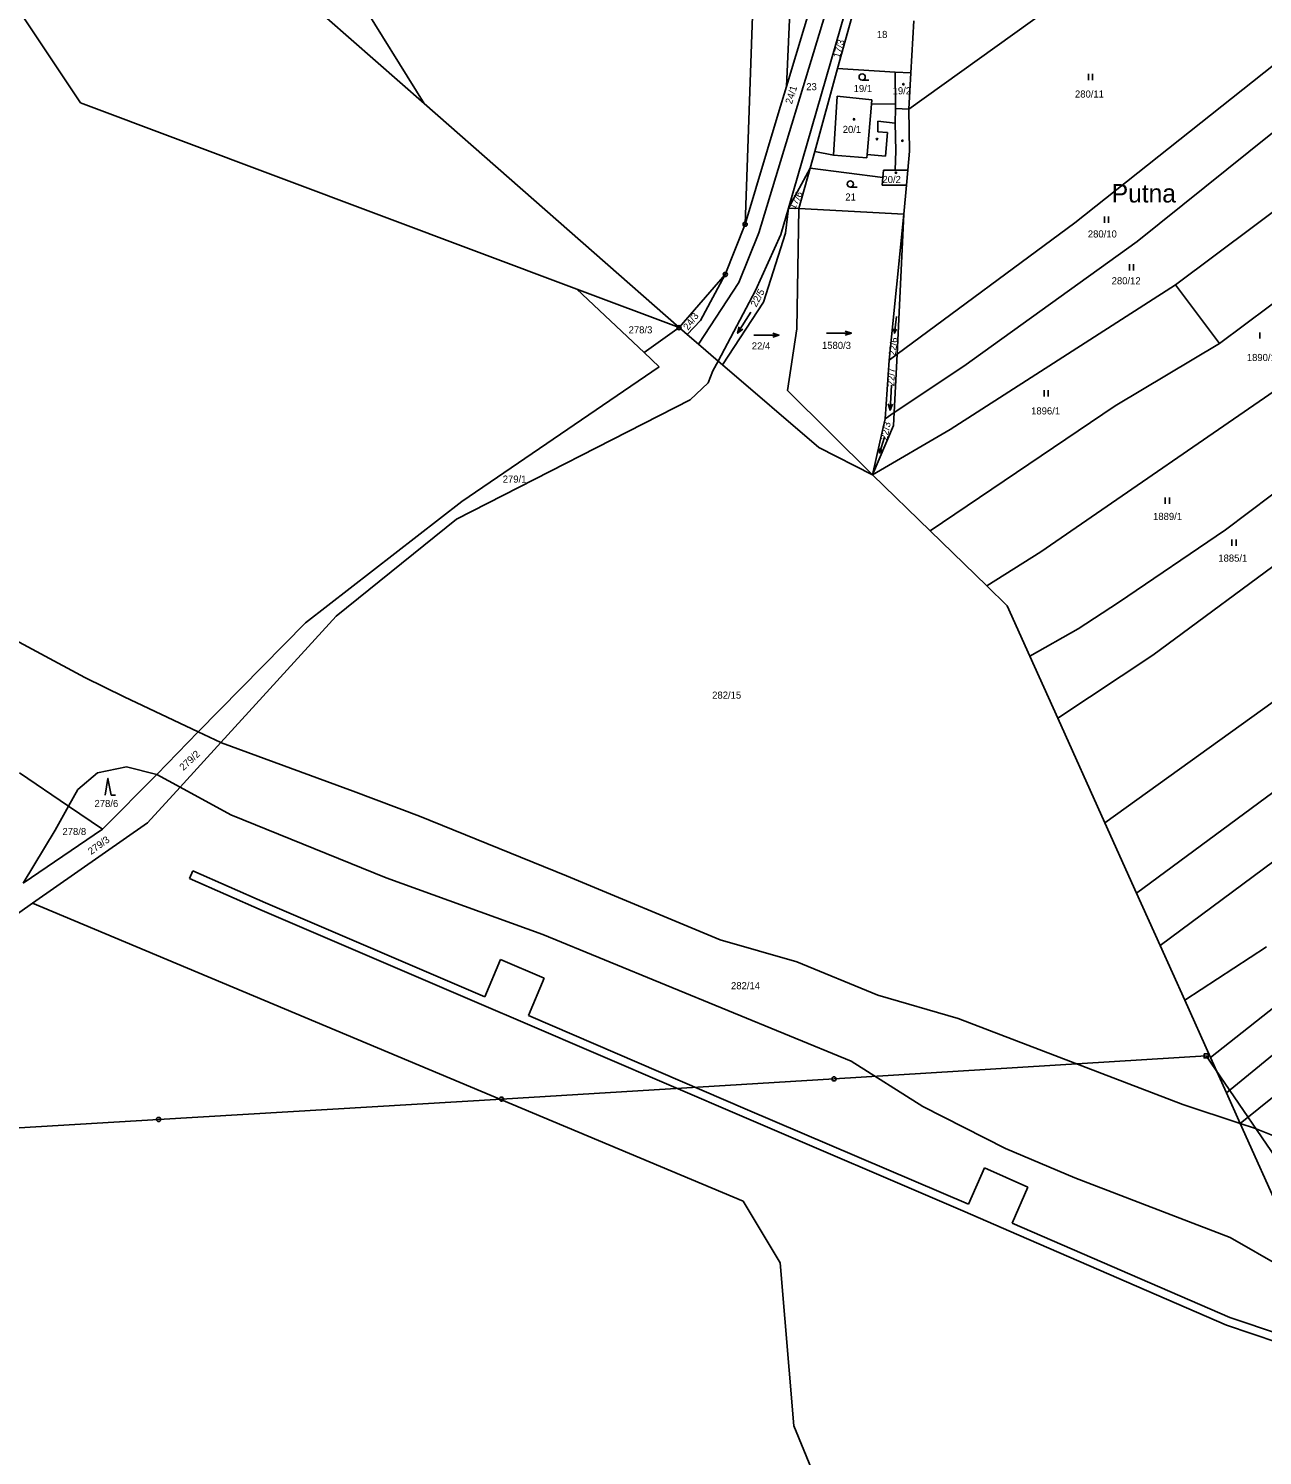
# Model space of a CAD drawing. Extents: x -762263 to -760336, y -1154405 to -1152076.
# Drawn here: x -761992.3 to -761696.3, y -1152903.3 to -1152561.1 of the extents above; entities that cross this region are included whole.
import ezdxf

# ---------------------------------------------------------------- set-up
doc = ezdxf.new("R2010")
doc.units = 0
for name, color, linetype in [('Vrstva 1', 7, 'Continuous'), ('Vrstva 12', 7, 'Continuous'), ('Vrstva 15', 7, 'Continuous'), ('Vrstva 18', 7, 'Continuous'), ('Vrstva 19', 7, 'Continuous'), ('Vrstva 24', 7, 'Continuous'), ('Vrstva 25', 7, 'Continuous'), ('Vrstva 26', 7, 'Continuous'), ('Vrstva 4', 7, 'Continuous'), ('Vrstva 6', 7, 'Continuous')]:
    doc.layers.add(name, color=color, linetype=linetype)

msp = doc.modelspace()

# ---------------------------------------------------------------- linework, layer by layer
at = {"layer": 'Vrstva 1'}
for p, q in [((-761816.98, -1152512.11), (-761820.4, -1152608.02)), ((-761971.53, -1152513.93), (-761897.36, -1152579.11)), ((-761817.12, -1152610.13), (-761793.65, -1152532.71)), ((-762008.34, -1152536.1), (-761979.81, -1152578.93)), ((-761810.02, -1152604.15), (-761790.04, -1152534.85)), ((-761721.98, -1152537.97), (-761781.14, -1152580.45)), ((-761798.23, -1152570.67), (-761792.59, -1152550.46)), ((-761780.62, -1152571.75), (-761779.95, -1152559.21)), ((-761803.71, -1152590.57), (-761798.23, -1152570.67)), ((-761798.23, -1152570.67), (-761784.38, -1152571.52)), ((-761784.38, -1152571.52), (-761780.62, -1152571.75)), ((-761784.32, -1152579.13), (-761784.38, -1152571.52)), ((-761780.62, -1152571.75), (-761781.14, -1152580.45)), ((-761860.79, -1152623.61), (-761979.81, -1152578.93)), ((-761897.36, -1152579.11), (-761836.24, -1152632.82)), ((-761798.33, -1152577.35), (-761799.22, -1152591.49)), ((-761790, -1152578.21), (-761798.33, -1152577.35)), ((-761790.1, -1152579.22), (-761790, -1152578.21)), ((-761784.32, -1152579.13), (-761790.1, -1152579.22)), ((-761784.31, -1152580.27), (-761784.32, -1152579.13)), ((-761781.14, -1152580.45), (-761784.31, -1152580.27)), ((-761780.94, -1152590.48), (-761781.14, -1152580.45)), ((-761804.8, -1152594.57), (-761803.71, -1152590.57)), ((-761799.22, -1152591.49), (-761803.71, -1152590.57)), ((-761781.36, -1152595.08), (-761780.94, -1152590.48)), ((-761670.53, -1152587.64), (-761717.16, -1152622.54)), ((-761807.48, -1152604.29), (-761804.8, -1152594.57)), ((-761804.8, -1152594.57), (-761787.37, -1152596.85)), ((-761787.37, -1152596.85), (-761787.55, -1152598.65)), ((-761787.19, -1152595.04), (-761787.37, -1152596.85)), ((-761784.44, -1152595.06), (-761787.19, -1152595.04)), ((-761781.36, -1152595.08), (-761784.44, -1152595.06)), ((-761781.69, -1152598.66), (-761781.36, -1152595.08)), ((-761781.69, -1152598.66), (-761787.55, -1152598.65)), ((-761782.33, -1152605.63), (-761781.69, -1152598.66)), ((-761810.02, -1152604.15), (-761811.86, -1152610.53)), ((-761807.48, -1152604.29), (-761810.02, -1152604.15)), ((-761782.33, -1152605.63), (-761807.48, -1152604.29)), ((-761706.64, -1152636.65), (-761659.83, -1152601.72)), ((-761825.15, -1152620.07), (-761820.4, -1152608.02)), ((-761782.33, -1152605.63), (-761783.97, -1152639.19)), ((-761821.89, -1152622.04), (-761817.12, -1152610.13)), ((-761817.91, -1152623.93), (-761811.86, -1152610.53)), ((-761836.24, -1152632.82), (-761825.15, -1152620.07)), ((-761836.24, -1152632.82), (-761860.79, -1152623.61)), ((-761844.63, -1152638.78), (-761860.79, -1152623.61)), ((-761831.6, -1152636.81), (-761821.89, -1152622.04)), ((-761826.89, -1152640.86), (-761817.91, -1152623.93)), ((-761706.64, -1152636.65), (-761717.16, -1152622.54)), ((-761836.24, -1152632.82), (-761844.63, -1152638.78)), ((-761834.27, -1152634.51), (-761836.24, -1152632.82)), ((-761831.6, -1152636.81), (-761834.27, -1152634.51)), ((-761840.99, -1152642.2), (-761844.63, -1152638.78)), ((-761831.6, -1152636.81), (-761826.89, -1152640.86)), ((-761888.32, -1152674.54), (-761840.99, -1152642.2)), ((-761828.12, -1152643.18), (-761826.89, -1152640.86)), ((-761826.89, -1152640.86), (-761825.81, -1152641.78)), ((-761802.74, -1152661.6), (-761825.81, -1152641.78)), ((-761783.97, -1152639.19), (-761784.65, -1152653.15)), ((-761829.24, -1152646.1), (-761828.12, -1152643.18)), ((-761833.6, -1152650.17), (-761829.24, -1152646.1)), ((-761889.59, -1152678.77), (-761833.6, -1152650.17)), ((-761784.65, -1152653.15), (-761784.81, -1152656.32)), ((-761789.86, -1152668.14), (-761784.81, -1152656.32)), ((-761802.74, -1152661.6), (-761789.86, -1152668.14)), ((-761789.86, -1152668.14), (-761776.05, -1152681.57)), ((-761925.83, -1152703.65), (-761888.32, -1152674.54)), ((-761889.59, -1152678.77), (-761918.45, -1152702.03)), ((-761776.05, -1152681.57), (-761762.46, -1152694.78)), ((-761635.48, -1152680.7), (-761734.11, -1152751.6)), ((-761762.46, -1152694.78), (-761757.53, -1152699.58)), ((-761752.1, -1152711.64), (-761757.53, -1152699.58)), ((-762008.53, -1152700.8), (-761978.76, -1152716.74)), ((-761925.83, -1152703.65), (-761951.56, -1152729.76)), ((-761918.45, -1152702.03), (-761946.15, -1152732.31)), ((-761745.41, -1152726.49), (-761752.1, -1152711.64)), ((-761978.76, -1152716.74), (-761969.35, -1152721.4)), ((-761951.56, -1152729.76), (-761969.35, -1152721.4)), ((-761734.11, -1152751.6), (-761745.41, -1152726.49)), ((-761951.56, -1152729.76), (-761961.5, -1152739.99)), ((-761946.15, -1152732.31), (-761951.56, -1152729.76)), ((-761946.15, -1152732.31), (-761955.94, -1152743.01)), ((-761946.15, -1152732.31), (-761945.97, -1152732.39)), ((-761945.97, -1152732.39), (-761914.39, -1152744)), ((-761994.44, -1152739.57), (-761982.68, -1152747.59)), ((-761980.46, -1152743.57), (-761975.76, -1152739.58)), ((-761975.76, -1152739.58), (-761968.74, -1152738.14)), ((-761961.5, -1152739.99), (-761974.57, -1152753.12)), ((-761961.5, -1152739.99), (-761968.74, -1152738.14)), ((-761955.94, -1152743.01), (-761961.5, -1152739.99)), ((-761982.68, -1152747.59), (-761980.46, -1152743.57)), ((-761955.94, -1152743.01), (-761963.76, -1152751.56)), ((-761955.94, -1152743.01), (-761943.75, -1152749.64)), ((-761914.39, -1152744), (-761898.53, -1152749.98)), ((-761985.87, -1152753.36), (-761982.68, -1152747.59)), ((-761974.57, -1152753.12), (-761982.68, -1152747.59)), ((-761991.29, -1152770.87), (-761963.76, -1152751.56)), ((-761943.75, -1152749.64), (-761906.53, -1152764.81)), ((-761898.53, -1152749.98), (-761863.26, -1152764.27)), ((-761734.11, -1152751.6), (-761726.5, -1152768.5)), ((-761974.57, -1152753.12), (-761993.53, -1152766.06)), ((-761993.53, -1152766.06), (-761985.87, -1152753.36)), ((-761952.86, -1152763.13), (-761953.66, -1152764.96)), ((-761953.66, -1152764.96), (-761936.2, -1152772.6)), ((-761935.4, -1152770.77), (-761952.86, -1152763.13)), ((-761906.53, -1152764.81), (-761868.88, -1152778.36)), ((-761863.26, -1152764.27), (-761826.38, -1152779.66)), ((-761726.5, -1152768.5), (-761720.86, -1152781.03)), ((-762001.57, -1152778.08), (-761991.29, -1152770.87)), ((-761820.89, -1152842.32), (-761991.29, -1152770.87)), ((-761882.87, -1152793.3), (-761935.4, -1152770.77)), ((-761936.2, -1152772.6), (-761883.65, -1152795.13)), ((-761868.88, -1152778.36), (-761794.95, -1152808.74)), ((-761826.38, -1152779.66), (-761808, -1152784.91)), ((-761720.86, -1152781.03), (-761714.94, -1152794.16)), ((-761879.04, -1152784.38), (-761882.87, -1152793.3)), ((-761868.56, -1152788.88), (-761879.04, -1152784.38)), ((-761808, -1152784.91), (-761788.59, -1152792.9)), ((-761872.39, -1152797.8), (-761868.56, -1152788.88)), ((-761883.65, -1152795.13), (-761873.18, -1152799.63)), ((-761788.59, -1152792.9), (-761769.32, -1152798.54)), ((-761714.94, -1152794.16), (-761708.78, -1152807.84)), ((-761873.18, -1152799.63), (-761820.62, -1152822.22)), ((-761819.83, -1152820.39), (-761872.39, -1152797.8)), ((-761769.32, -1152798.54), (-761715.38, -1152819.17)), ((-761794.95, -1152808.74), (-761777.78, -1152819.59)), ((-761708.78, -1152807.84), (-761704.93, -1152816.38)), ((-761704.93, -1152816.38), (-761701.64, -1152823.7)), ((-761777.78, -1152819.59), (-761757.91, -1152829.7)), ((-761715.38, -1152819.17), (-761701.64, -1152823.7)), ((-761820.62, -1152822.22), (-761767.61, -1152844.9)), ((-761766.8, -1152843.07), (-761819.83, -1152820.39)), ((-761691.51, -1152846.21), (-761701.64, -1152823.7)), ((-761701.64, -1152823.7), (-761698.2, -1152824.84)), ((-761698.2, -1152824.84), (-761679.85, -1152832.21)), ((-761757.91, -1152829.7), (-761741.31, -1152836.75)), ((-761762.99, -1152834.37), (-761766.8, -1152843.07)), ((-761752.55, -1152838.94), (-761762.99, -1152834.37)), ((-761741.31, -1152836.75), (-761704.08, -1152851.01)), ((-761756.36, -1152847.64), (-761752.55, -1152838.94)), ((-761811.96, -1152857.14), (-761820.89, -1152842.32)), ((-761767.61, -1152844.9), (-761757.16, -1152849.47)), ((-761757.16, -1152849.47), (-761704.92, -1152872.08)), ((-761704.12, -1152870.25), (-761756.36, -1152847.64)), ((-761704.08, -1152851.01), (-761691.53, -1152858.2)), ((-761808.73, -1152896.24), (-761811.96, -1152857.14)), ((-761691.97, -1152874.29), (-761704.12, -1152870.25)), ((-761704.92, -1152872.08), (-761692.6, -1152876.19)), ((-761769.11, -1152991.53), (-761808.73, -1152896.24))]:
    msp.add_line(p, q, dxfattribs=at)
at = {"layer": 'Vrstva 12'}
for p, q in [((-761709.8, -1152807.49), (-761799.07, -1152813)), ((-761644.75, -1152902.92), (-761709.8, -1152807.49)), ((-761799.07, -1152813), (-761878.83, -1152817.85)), ((-761878.83, -1152817.85), (-761961.09, -1152822.73)), ((-761961.09, -1152822.73), (-762045.29, -1152827.8))]:
    msp.add_line(p, q, dxfattribs=at)
at = {"layer": 'Vrstva 24'}
for centre, radius in [((-761820.4, -1152608.02), 0.5), ((-761820.4, -1152608.02), 0.1), ((-761825.15, -1152620.07), 0.5), ((-761825.15, -1152620.07), 0.1), ((-761836.24, -1152632.82), 0.5), ((-761836.24, -1152632.82), 0.1)]:
    msp.add_circle(centre, radius, dxfattribs=at)
at = {"layer": 'Vrstva 25'}
for p, q in [((-761792.33, -1152573.47), (-761790.73, -1152573.47)), ((-761738.06, -1152573.46), (-761738.06, -1152571.96)), ((-761737.06, -1152573.46), (-761737.06, -1152571.96)), ((-761795.16, -1152599.15), (-761793.56, -1152599.15)), ((-761734.23, -1152607.69), (-761734.23, -1152606.19)), ((-761733.23, -1152607.69), (-761733.23, -1152606.19)), ((-761728.23, -1152619.1), (-761728.23, -1152617.6)), ((-761727.23, -1152619.1), (-761727.23, -1152617.6)), ((-761696.94, -1152635.47), (-761696.94, -1152633.97)), ((-761748.71, -1152649.35), (-761748.71, -1152647.85)), ((-761747.71, -1152649.35), (-761747.71, -1152647.85)), ((-761719.63, -1152675.08), (-761719.63, -1152673.58)), ((-761718.63, -1152675.08), (-761718.63, -1152673.58)), ((-761703.64, -1152685.13), (-761703.64, -1152683.63)), ((-761702.64, -1152685.13), (-761702.64, -1152683.63))]:
    msp.add_line(p, q, dxfattribs=at)
for points in [[(-761819.003, -1152629.09), (-761822.197, -1152634.17), (-761820.975, -1152633.166)], [(-761784.061, -1152630.177), (-761784.579, -1152634.163), (-761784.117, -1152633.21)], [(-761822.197, -1152634.17), (-761821.822, -1152632.634)], [(-761818.28, -1152634.62), (-761812.28, -1152634.62), (-761813.78, -1152634.12)], [(-761812.28, -1152634.62), (-761813.78, -1152635.12)], [(-761800.9, -1152634.14), (-761794.9, -1152634.14), (-761796.4, -1152633.64)], [(-761794.9, -1152634.14), (-761796.4, -1152634.64)], [(-761784.579, -1152634.163), (-761784.782, -1152633.123)], [(-761785.276, -1152646.636), (-761785.644, -1152652.624), (-761785.053, -1152651.158)], [(-761785.644, -1152652.624), (-761786.051, -1152651.096)], [(-761786.998, -1152659.072), (-761788.202, -1152662.908), (-761787.582, -1152662.049)], [(-761788.202, -1152662.908), (-761788.221, -1152661.848)], [(-761973.92, -1152744.93), (-761973.22, -1152740.93), (-761972.42, -1152744.93), (-761971.42, -1152744.93)]]:
    msp.add_lwpolyline(points, dxfattribs=at)
for centre, radius in [((-761792.33, -1152572.72), 0.75), ((-761782.42, -1152574.44), 0.175), ((-761794.25, -1152582.86), 0.175), ((-761788.76, -1152587.62), 0.175), ((-761782.66, -1152588.01), 0.175), ((-761795.16, -1152598.4), 0.75), ((-761784.23, -1152595.68), 0.175)]:
    msp.add_circle(centre, radius, dxfattribs=at)
at = {"layer": 'Vrstva 26'}
msp.add_lwpolyline([(-761710.3, -1152806.99), (-761709.3, -1152806.99), (-761709.3, -1152807.99), (-761710.3, -1152807.99)], close=True, dxfattribs=at)
for centre in [(-761799.07, -1152813), (-761878.83, -1152817.85), (-761961.09, -1152822.73)]:
    msp.add_circle(centre, 0.5, dxfattribs=at)
at = {"layer": 'Vrstva 4'}
for p, q in [((-761791.11, -1152591.34), (-761790.1, -1152579.22)), ((-761784.31, -1152580.27), (-761784.4, -1152583.81)), ((-761788.54, -1152585.86), (-761788.54, -1152583.34)), ((-761788.54, -1152583.34), (-761784.4, -1152583.81)), ((-761784.4, -1152583.81), (-761784.24, -1152590.46)), ((-761786.26, -1152586.05), (-761788.54, -1152585.86)), ((-761786.74, -1152591.71), (-761786.26, -1152586.05)), ((-761784.24, -1152590.46), (-761784.44, -1152595.06)), ((-761799.22, -1152591.49), (-761791.22, -1152592.1)), ((-761791.22, -1152592.1), (-761791.11, -1152591.34)), ((-761791.11, -1152591.34), (-761786.74, -1152591.71))]:
    msp.add_line(p, q, dxfattribs=at)
at = {"layer": 'Vrstva 6'}
for p, q in [((-761807.84, -1152512.8), (-761810.44, -1152575.01)), ((-761810.44, -1152575.01), (-761797.1, -1152530.14)), ((-761920.34, -1152542.17), (-761897.36, -1152579.11)), ((-761741.33, -1152607.69), (-761686.92, -1152564.53)), ((-761812.46, -1152581.58), (-761810.44, -1152575.01)), ((-761726.39, -1152612.2), (-761679.66, -1152574.65)), ((-761820.4, -1152608.02), (-761812.46, -1152581.58)), ((-761810.02, -1152604.15), (-761804.8, -1152594.57)), ((-761810.68, -1152610.21), (-761810.02, -1152604.15)), ((-761807.48, -1152604.29), (-761807.99, -1152633.1)), ((-761785.82, -1152640.65), (-761782.33, -1152605.63)), ((-761783.97, -1152639.19), (-761741.33, -1152607.69)), ((-761816.03, -1152626.7), (-761810.68, -1152610.21)), ((-761767.93, -1152642.05), (-761726.39, -1152612.2)), ((-761825.15, -1152620.07), (-761831.13, -1152631.13)), ((-761717.16, -1152622.54), (-761771.24, -1152657.28)), ((-761825.81, -1152641.78), (-761816.03, -1152626.7)), ((-761831.13, -1152631.13), (-761834.27, -1152634.51)), ((-761807.99, -1152633.1), (-761810.21, -1152647.87)), ((-761672.04, -1152633.28), (-761749.48, -1152686.56)), ((-761731.61, -1152651.62), (-761706.64, -1152636.65)), ((-761786.82, -1152654.71), (-761785.82, -1152640.65)), ((-761785.82, -1152640.65), (-761783.97, -1152639.19)), ((-761784.65, -1152653.15), (-761767.93, -1152642.05)), ((-761705.17, -1152681.31), (-761655.88, -1152644.04)), ((-761789.86, -1152668.14), (-761810.21, -1152647.87)), ((-761776.05, -1152681.57), (-761731.61, -1152651.62)), ((-761788.12, -1152660.26), (-761786.82, -1152654.71)), ((-761786.82, -1152654.71), (-761784.65, -1152653.15)), ((-761771.24, -1152657.28), (-761789.86, -1152668.14)), ((-761789.86, -1152668.14), (-761788.12, -1152660.26)), ((-761722.61, -1152711.41), (-761665.99, -1152669.46)), ((-761705.17, -1152681.31), (-761730.86, -1152698.76)), ((-761749.48, -1152686.56), (-761762.46, -1152694.78)), ((-761730.86, -1152698.76), (-761740.49, -1152705.1)), ((-761726.5, -1152768.5), (-761630.46, -1152697.29)), ((-761740.49, -1152705.1), (-761752.1, -1152711.64)), ((-761745.41, -1152726.49), (-761722.61, -1152711.41)), ((-761648.55, -1152727.31), (-761720.86, -1152781.03)), ((-761695.32, -1152781.37), (-761714.94, -1152794.16)), ((-761677.64, -1152783.3), (-761708.78, -1152807.84)), ((-761669.03, -1152786.8), (-761704.93, -1152816.38)), ((-761701.64, -1152823.7), (-761657.88, -1152788.29))]:
    msp.add_line(p, q, dxfattribs=at)

# ---------------------------------------------------------------- texts
at = {"layer": 'Vrstva 15'}
msp.add_text('Putna', height=4.4, dxfattribs=at).set_placement((-761732.448, -1152602.81))
at = {"layer": 'Vrstva 18'}
for s, p in [('18', (-761788.817, -1152563.36)), ('23', (-761805.736, -1152575.89)), ('19/1', (-761794.368, -1152576.32)), ('280/11', (-761741.284, -1152577.65)), ('21', (-761796.36, -1152602.35)), ('280/10', (-761738.198, -1152611.21)), ('280/12', (-761732.485, -1152622.44)), ('278/3', (-761848.343, -1152634.2)), ('22/4', (-761818.801, -1152638.07)), ('1580/3', (-761801.962, -1152637.93)), ('1890/1', (-761700.07, -1152640.83)), ('1896/1', (-761751.803, -1152653.65)), ('279/1', (-761878.533, -1152670)), ('1889/1', (-761722.55, -1152678.95)), ('1885/1', (-761706.907, -1152688.95)), ('282/15', (-761828.303, -1152721.81)), ('278/6', (-761976.453, -1152747.8)), ('278/8', (-761984.143, -1152754.52)), ('282/14', (-761823.783, -1152791.5))]:
    msp.add_text(s, height=1.7, dxfattribs=at).set_placement(p)
for s, rotation, p in [('17/3', 74.6564, (-761797.706, -1152568.276)), ('24/1', 72.76564, (-761809.192, -1152579.339)), ('17/6', 63.42643, (-761808.484, -1152604.627)), ('22/5', 61.76485, (-761817.72, -1152628.028)), ('24/3', 53.51426, (-761834.057, -1152633.585)), ('22/6', 83.47995, (-761784.308, -1152639.672)), ('22/7', 87.08959, (-761784.655, -1152646.907)), ('22/3', 78.49522, (-761786.324, -1152659.968)), ('279/2', 43.14372, (-761955.137, -1152739.188)), ('279/3', 35.92445, (-761977.258, -1152759.341))]:
    msp.add_text(s, height=1.7, rotation=rotation, dxfattribs=at).set_placement(p)
at = {"layer": 'Vrstva 19'}
for s, p in [('19/2', (-761785.019, -1152576.86)), ('20/1', (-761796.986, -1152586.13)), ('20/2', (-761787.468, -1152598.14))]:
    msp.add_text(s, height=1.7, dxfattribs=at).set_placement(p)

doc.saveas('drawing.dxf')
